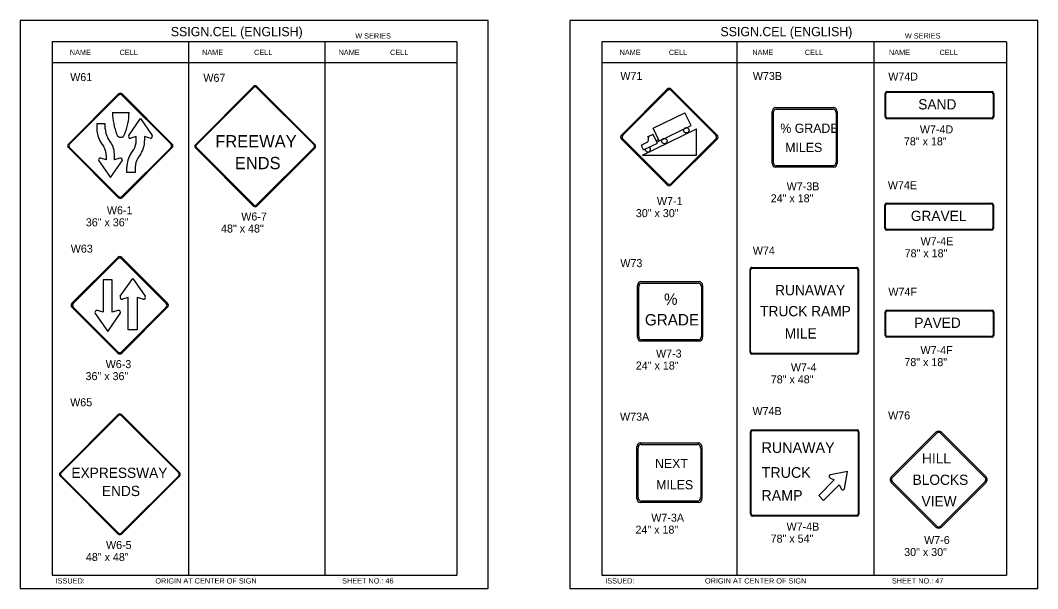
# Model space of a CAD drawing. Extents: x -5299 to 22597, y -19549 to -1808.
# Drawn here: x 2593 to 4118, y -4545 to -3692 of the extents above; entities that cross this region are included whole.
import ezdxf

# ---------------------------------------------------------------- set-up
doc = ezdxf.new("R2010")
doc.units = 0
for name, color, linetype in [('Level 1', 7, 'Continuous'), ('Level 2', 7, 'Continuous'), ('Level 3', 7, 'Continuous'), ('Level 62', 7, 'Continuous')]:
    doc.layers.add(name, color=color, linetype=linetype)

msp = doc.modelspace()

# ---------------------------------------------------------------- linework, layer by layer
at = {"layer": 'Level 1'}
for p, q in [((3247.7, -3724.4), (2640.7, -3724.4)), ((2640.7, -3724.4), (2640.7, -4524.4)), ((2845.3, -3724.4), (2845.3, -4524.4)), ((3049.7, -3725.3), (3049.7, -4525.3)), ((3247.7, -3724.4), (3247.7, -4524.4)), ((4071.6, -3724.4), (3464.6, -3724.4)), ((3464.6, -3724.4), (3464.6, -4524.4)), ((3667, -3724.4), (3667, -4524.4)), ((3872.8, -3723.2), (3872.8, -4523.2)), ((4071.6, -3724.4), (4071.6, -4524.4)), ((3247.7, -3756), (2640.7, -3756)), ((4071.6, -3756), (3464.6, -3756)), ((2855.5, -3878.7), (2942.9, -3791.3)), ((2857.1, -3878.9), (2943.1, -3792.8)), ((2947.3, -3792.8), (3033.4, -3878.9)), ((2947.5, -3791.3), (3034.9, -3878.7)), ((3494.3, -3864.2), (3563, -3795.5)), ((3569, -3795.5), (3637.8, -3864.2)), ((2665.1, -3877.7), (2740.3, -3802.5)), ((2666.9, -3877.9), (2740.5, -3804.3)), ((2745.4, -3804.3), (2819, -3877.9)), ((2745.7, -3802.5), (2820.8, -3877.7)), ((3496.3, -3864.5), (3563.3, -3797.4)), ((3568.8, -3797.4), (3635.8, -3864.5)), ((3889.6, -3837), (3889.6, -3801.7)), ((3890.6, -3836.2), (3890.6, -3802.5)), ((3892.1, -3799), (4049.8, -3799)), ((3892.8, -3800), (4049, -3800)), ((4051.3, -3802.5), (4051.3, -3836.2)), ((4052.3, -3801.7), (4052.3, -3837)), ((3725, -3823.1), (3812.8, -3823.1)), ((3726.4, -3825.4), (3811.4, -3825.4)), ((3971.4, -3819), (3971.4, -3819)), ((2731.2, -3830.2), (2756.1, -3830.2)), ((2755.7, -3864.7), (2773.2, -3839.5)), ((2755.7, -3864.7), (2773.2, -3839.5)), ((2773.2, -3839.5), (2790.6, -3864.7)), ((2773.2, -3839.5), (2790.6, -3864.7)), ((3541.8, -3854), (3589.2, -3830.9)), ((3598.6, -3850.1), (3589.2, -3830.9)), ((3720.1, -3906.6), (3720.1, -3829.1)), ((3722, -3904.9), (3722, -3830.8)), ((3815.9, -3830.8), (3815.9, -3904.9)), ((3817.7, -3829.1), (3817.7, -3906.6)), ((4049.8, -3839.7), (3892.1, -3839.7)), ((4049, -3838.7), (3892.8, -3838.7)), ((2707.9, -3847.2), (2707.9, -3855)), ((2720.4, -3847.2), (2707.9, -3847.2)), ((2720.4, -3855), (2720.4, -3847.2)), ((3525.6, -3894.6), (3606.8, -3855)), ((3551, -3872.8), (3541.8, -3854)), ((3547.5, -3875), (3598.6, -3850.1)), ((3606.8, -3894.6), (3606.8, -3855)), ((2728.5, -3874.9), (2724.3, -3868.5)), ((2767, -3866.2), (2758.8, -3868.8)), ((2767, -3866.2), (2758.8, -3868.8)), ((2767, -3872.4), (2767, -3866.2)), ((2787.5, -3868.8), (2779.4, -3866.2)), ((2779.4, -3866.2), (2779.4, -3872.4)), ((3563, -3939), (3494.3, -3870.2)), ((3563.3, -3937), (3496.3, -3870)), ((3533.5, -3866.8), (3541.7, -3862.8)), ((3534.7, -3866.2), (3533.7, -3874.4)), ((3548.2, -3876.4), (3541.5, -3862.7)), ((3546.9, -3872.3), (3550.2, -3870.7)), ((3565.9, -3866.9), (3565.9, -3866.9)), ((3635.8, -3870), (3568.8, -3937)), ((3637.8, -3870.2), (3569, -3939)), ((3768.6, -3866.8), (3768.6, -3866.8)), ((2740.3, -3958.2), (2665.1, -3883)), ((2740.5, -3956.4), (2666.9, -3882.8)), ((2713.8, -3875.2), (2718.1, -3881.7)), ((2743, -3880.4), (2743, -3880.4)), ((2819, -3882.8), (2745.4, -3956.4)), ((2820.8, -3883), (2745.7, -3958.2)), ((2758.9, -3892.3), (2763.1, -3885.8)), ((2942.9, -3970.7), (2855.5, -3883.3)), ((2943.1, -3969.1), (2857.1, -3883.1)), ((2945.2, -3881), (2945.2, -3881)), ((3033.4, -3883.1), (2947.3, -3969.1)), ((3034.9, -3883.3), (2947.5, -3970.7)), ((3527.4, -3886.6), (3524.4, -3880.4)), ((3525, -3878.7), (3533.7, -3874.4)), ((3527.4, -3886.6), (3548.2, -3876.4)), ((2710.6, -3902.8), (2728.1, -3928)), ((2721.9, -3901.3), (2713.7, -3898.7)), ((2721.9, -3895.1), (2721.9, -3901.3)), ((2728.1, -3928), (2745.6, -3902.8)), ((2734.3, -3901.3), (2734.3, -3895.1)), ((2742.5, -3898.7), (2734.3, -3901.3)), ((2773.6, -3892.6), (2769.4, -3899)), ((3525.6, -3894.6), (3606.8, -3894.6)), ((2753, -3920.3), (2753, -3912.5)), ((2765.4, -3912.5), (2765.4, -3920.3)), ((3812.8, -3912.6), (3725, -3912.6)), ((3811.4, -3910.4), (3726.4, -3910.4)), ((2765.4, -3920.3), (2753, -3920.3)), ((3889.3, -4004.3), (3889.3, -3969)), ((3890.2, -4003.5), (3890.2, -3969.8)), ((3891.8, -3966.3), (4049.4, -3966.3)), ((3892.5, -3967.3), (4048.7, -3967.3)), ((4051, -3969.8), (4051, -4003.5)), ((4051.9, -3969), (4051.9, -4004.3)), ((3971.4, -3985.4), (3971.4, -3985.4)), ((4049.4, -4007), (3891.8, -4007)), ((4048.7, -4006), (3892.5, -4006)), ((2670.4, -4116.6), (2739.2, -4047.8)), ((2672.4, -4116.8), (2739.4, -4049.8)), ((2744.9, -4049.8), (2811.9, -4116.8)), ((2745.1, -4047.8), (2813.9, -4116.6)), ((3687, -4189.6), (3687, -4066)), ((3687, -4189.6), (3687, -4066)), ((3687.9, -4188.7), (3687.9, -4067)), ((3689.5, -4062.8), (3847.1, -4062.8)), ((3689.5, -4062.8), (3847.1, -4062.8)), ((3690.2, -4064), (3846.4, -4064)), ((3848.7, -4067), (3848.7, -4188.7)), ((3849.6, -4066), (3849.6, -4189.6)), ((3849.6, -4066), (3849.6, -4189.6)), ((2730.7, -4081.3), (2717.5, -4081.3)), ((2717.5, -4081.3), (2717.5, -4130.1)), ((2730.7, -4130.1), (2730.7, -4081.3)), ((2743, -4106.1), (2761.8, -4079.2)), ((2761.8, -4079.2), (2780.3, -4106.1)), ((3523.2, -4084), (3611, -4084)), ((3524.6, -4086.2), (3609.6, -4086.2)), ((3518.3, -4167.5), (3518.3, -4089.9)), ((3520.2, -4165.8), (3520.2, -4091.7)), ((3614.1, -4091.7), (3614.1, -4165.8)), ((3615.9, -4089.9), (3615.9, -4167.5)), ((2755, -4107.8), (2746.3, -4110.5)), ((2755, -4156.6), (2755, -4107.8)), ((2777.1, -4110.5), (2768.4, -4107.8)), ((2768.4, -4107.8), (2768.4, -4156.6)), ((2739.2, -4191.3), (2670.4, -4122.6)), ((2739.4, -4189.3), (2672.4, -4122.3)), ((2705.3, -4131.8), (2724.1, -4158.8)), ((2717.5, -4130.1), (2708.7, -4127.5)), ((2724.1, -4158.8), (2742.7, -4131.8)), ((2739.4, -4127.5), (2730.7, -4130.1)), ((2741.7, -4119.5), (2741.7, -4119.5)), ((2811.9, -4122.3), (2744.9, -4189.3)), ((2813.9, -4122.6), (2745.1, -4191.3)), ((3567.2, -4128.7), (3567.2, -4128.7)), ((3768.2, -4128.4), (3768.2, -4128.4)), ((3889.6, -4164.7), (3889.6, -4129.5)), ((3890.6, -4163.9), (3890.6, -4130.3)), ((3892.1, -4126.8), (4049.8, -4126.8)), ((3892.8, -4127.8), (4049, -4127.8)), ((4051.3, -4130.3), (4051.3, -4163.9)), ((4052.3, -4129.5), (4052.3, -4164.7)), ((3970.7, -4145.4), (3970.7, -4145.4)), ((2768.4, -4156.6), (2755, -4156.6)), ((3611, -4173.5), (3523.2, -4173.5)), ((3609.6, -4171.2), (3524.6, -4171.2)), ((4049.8, -4167.4), (3892.1, -4167.4)), ((4049, -4166.4), (3892.8, -4166.4)), ((3847.1, -4192.9), (3689.5, -4192.9)), ((3847.1, -4192.9), (3689.5, -4192.9)), ((3847.1, -4192.9), (3689.5, -4192.9)), ((3846.4, -4191.6), (3690.2, -4191.6)), ((2652.6, -4370.7), (2740, -4283.3)), ((2654.2, -4370.9), (2740.2, -4284.8)), ((2744.4, -4284.8), (2830.5, -4370.9)), ((2744.6, -4283.3), (2832, -4370.7)), ((3687.6, -4432.1), (3687.6, -4309.1)), ((3688.5, -4432.1), (3688.5, -4309.9)), ((3690.1, -4306.1), (3847.7, -4306.1)), ((3690.8, -4307.2), (3847, -4307.2)), ((3849.3, -4309.9), (3849.3, -4432.1)), ((3850.2, -4309.1), (3850.2, -4432.9)), ((3898.6, -4376.8), (3965.5, -4309.9)), ((3900.1, -4378.2), (3966.9, -4311.3)), ((3972.6, -4311.3), (4039.4, -4378.2)), ((3974, -4309.9), (4040.8, -4376.8)), ((3522.1, -4325.9), (3610, -4325.9)), ((3523.6, -4328.1), (3608.5, -4328.1)), ((3517.3, -4409.4), (3517.3, -4331.9)), ((3519.1, -4407.7), (3519.1, -4333.6)), ((3613, -4333.6), (3613, -4407.7)), ((3614.8, -4331.9), (3614.8, -4409.4)), ((2740, -4462.7), (2652.6, -4375.3)), ((2740.2, -4461.1), (2654.2, -4375.1)), ((2742.4, -4373), (2742.4, -4373)), ((2830.5, -4375.1), (2744.4, -4461.1)), ((2832, -4375.3), (2744.6, -4462.7)), ((3566.9, -4370.7), (3566.9, -4370.7)), ((3768.8, -4370.7), (3768.8, -4370.7)), ((3833.1, -4369), (3807.4, -4373.8)), ((3828.5, -4394.8), (3833.1, -4369)), ((3813.2, -4381.5), (3789.9, -4404.8)), ((3797.3, -4412.3), (3820.7, -4388.9)), ((3806.8, -4378.1), (3813.2, -4381.5)), ((3820.7, -4388.9), (3824.1, -4395.4)), ((3965.5, -4452.1), (3898.6, -4385.3)), ((3966.9, -4450.7), (3900.1, -4383.9)), ((3969.6, -4381.3), (3969.6, -4381.3)), ((4039.4, -4383.9), (3972.6, -4450.7)), ((4040.8, -4385.3), (3974, -4452.1)), ((3789.9, -4404.8), (3797.3, -4412.3)), ((3610, -4415.4), (3522.1, -4415.4)), ((3608.5, -4413.2), (3523.6, -4413.2)), ((3847.7, -4435.9), (3690.1, -4435.9)), ((3847, -4434.8), (3690.8, -4434.8)), ((2640.7, -4524.4), (3247.7, -4524.4)), ((3464.6, -4524.4), (4071.6, -4524.4))]:
    msp.add_line(p, q, dxfattribs=at)
for centre in [(3591.5, -3857), (3558.6, -3873.2)]:
    msp.add_circle(centre, 4.03, dxfattribs=at)
for centre, radius, start, end in [((2945.2, -3793.6), 3.25, 45, 135), ((2945.2, -3794.9), 2.98, 45, 135), ((3566, -3798.4), 4.23, 45, 135), ((3566, -3800.2), 3.88, 45, 135), ((2743, -3805.2), 3.8, 45, 135), ((2743, -3806.8), 3.48, 45, 135), ((2825.1, -3828.8), 93.8, 180.8032, 201.7205), ((2662.1, -3828.8), 94, 338.2914, 359.1848), ((2745.5, -3854.9), 37.6, 180.1139, 212.7545), ((2745.3, -3855), 24.9, 180.0457, 212.8226), ((2743.7, -3861.2), 6.24, 202.1766, 337.8234), ((2758, -3866.2), 2.74, 147.86, 286.7479), ((2758, -3866.2), 2.74, 147.86, 286.7479), ((2741.8, -3872.4), 25.2, 327.9451, 359.8882), ((2741.6, -3872.4), 37.8, 327.7467, 359.8501), ((2788.3, -3866.2), 2.74, 253.2521, 32.14), ((3497.3, -3867.2), 4.23, 135, 225), ((3499, -3867.2), 3.88, 135, 225), ((3633.1, -3867.2), 3.88, 315, 45), ((3634.8, -3867.2), 4.23, 315, 45), ((2667.8, -3880.4), 3.8, 135, 225), ((2669.4, -3880.4), 3.48, 135, 225), ((2696.7, -3895.1), 25.2, 0.1119, 32.0549), ((2696.6, -3895.1), 37.8, 0.1499, 32.2533), ((2816.5, -3880.4), 3.48, 315, 45), ((2818.1, -3880.4), 3.8, 315, 45), ((2857.8, -3881), 3.25, 135, 225), ((2859.2, -3881), 2.98, 135, 225), ((3031.3, -3881), 2.98, 315, 45), ((3032.6, -3881), 3.25, 315, 45), ((3525.5, -3879.8), 1.27, 115.9906, 205.9854), ((3533.8, -3885.6), 4.03, 177.4374, 58.7156), ((2712.9, -3901.3), 2.74, 73.2521, 212.14), ((2743.3, -3901.3), 2.74, 327.86, 106.7479), ((2790.5, -3912.6), 37.6, 147.2455, 179.8861), ((2790.4, -3912.5), 24.9, 147.1774, 179.9543), ((3566, -3936), 4.23, 225, 315), ((3566, -3934.2), 3.88, 225, 315), ((2743, -3955.5), 3.8, 225, 315), ((2743, -3953.9), 3.48, 225, 315), ((2945.2, -3968.4), 3.25, 225, 315), ((2945.2, -3967), 2.98, 225, 315), ((2742.2, -4050.8), 4.23, 45, 135), ((2742.2, -4052.5), 3.88, 45, 135), ((2673.4, -4119.6), 4.23, 135, 225), ((2675.1, -4119.6), 3.88, 135, 225), ((2745.5, -4107.7), 2.92, 148.533, 286.6041), ((2777.9, -4107.7), 2.89, 252.0487, 32.8141), ((2809.2, -4119.6), 3.88, 315, 45), ((2810.9, -4119.6), 4.23, 315, 45), ((2707.9, -4130.3), 2.92, 73.3959, 211.467), ((2740.3, -4130.3), 2.89, 327.1859, 107.9513), ((2742.2, -4188.3), 4.23, 225, 315), ((2742.2, -4186.6), 3.88, 225, 315), ((2742.3, -4285.6), 3.25, 45, 135), ((2742.3, -4287), 2.98, 45, 135), ((3969.7, -4314.2), 6, 45.0004, 135.0002), ((3969.7, -4314.2), 4, 45.0004, 135.0002), ((2654.9, -4373), 3.25, 135, 225), ((2656.3, -4373), 2.98, 135, 225), ((2828.3, -4373), 2.98, 315, 45), ((2829.7, -4373), 3.25, 315, 45), ((3807.9, -4376), 2.3, 102.1859, 242.9513), ((3902.9, -4381), 6, 135.0002, 225.0004), ((4036.6, -4381), 6, 314.9998, 45.0004), ((3902.9, -4381), 4, 135.0002, 225.0004), ((4036.6, -4381), 4, 314.9998, 45.0004), ((3826.2, -4394.2), 2.32, 208.3959, 346.467), ((3969.7, -4447.9), 6, 225.0004, 314.9998), ((3969.7, -4447.9), 4, 225.0004, 314.9998), ((2742.3, -4460.4), 3.25, 225, 315), ((2742.3, -4459), 2.98, 225, 315)]:
    msp.add_arc(centre, radius, start, end, dxfattribs=at)
for centre, major_axis, ratio, start_param, end_param in [((3892.1, -3801.7), (0, -2.71), 0.923079, 3.141593, 4.712389), ((3892.8, -3802.5), (0, 2.48), 0.923079, 0, 1.570796), ((4049, -3802.5), (0, 2.48), 0.923079, 4.712389, 6.283185), ((4049.8, -3801.7), (0, 2.71), 0.923079, 4.712389, 6.283185), ((3725, -3829.1), (0, -5.97), 0.817773, 3.141593, 4.712389), ((3726.4, -3830.8), (0, 5.47), 0.817773, 0, 1.570796), ((3811.4, -3830.8), (0, 5.47), 0.817773, 4.712389, 6.283185), ((3812.8, -3829.1), (0, 5.97), 0.817773, 4.712389, 6.283185), ((3892.1, -3837), (0, -2.71), 0.923079, 4.712389, 6.283185), ((3892.8, -3836.2), (0, -2.48), 0.923079, 4.712389, 6.283185), ((4049, -3836.2), (0, -2.48), 0.923079, 0, 1.570796), ((4049.8, -3837), (0, 2.71), 0.923079, 3.141593, 4.712389), ((3725, -3906.6), (0, -5.97), 0.817773, 4.712389, 6.283185), ((3726.4, -3904.9), (0, -5.47), 0.817773, 4.712389, 6.283185), ((3811.4, -3904.9), (0, -5.47), 0.817773, 0, 1.570796), ((3812.8, -3906.6), (0, -5.97), 0.817773, 0, 1.570796), ((3891.8, -3969), (0, -2.71), 0.923079, 3.141593, 4.712389), ((3892.5, -3969.8), (0, 2.48), 0.923079, 0, 1.570796), ((4048.7, -3969.8), (0, 2.48), 0.923079, 4.712389, 6.283185), ((4049.4, -3969), (0, 2.71), 0.923079, 4.712389, 6.283185), ((3891.8, -4004.3), (0, -2.71), 0.923079, 4.712389, 6.283185), ((3892.5, -4003.5), (0, -2.48), 0.923079, 4.712389, 6.283185), ((4048.7, -4003.5), (0, -2.48), 0.923079, 0, 1.570796), ((4049.4, -4004.3), (0, 2.71), 0.923079, 3.141593, 4.712389), ((3689.5, -4066), (0, -3.25), 0.769225, 3.141593, 4.712389), ((3689.5, -4066), (0, -3.25), 0.769225, 3.141593, 4.712389), ((3690.2, -4067), (0, -2.98), 0.769225, 3.141593, 4.712389), ((3846.4, -4067), (0, 2.98), 0.769225, 4.712389, 6.283185), ((3847.1, -4066), (0, 3.25), 0.769225, 4.712389, 6.283185), ((3847.1, -4066), (0, 3.25), 0.769225, 4.712389, 6.283185), ((3523.2, -4089.9), (0, -5.97), 0.817773, 3.141593, 4.712389), ((3524.6, -4091.7), (0, 5.47), 0.817773, 0, 1.570796), ((3609.6, -4091.7), (0, 5.47), 0.817773, 4.712389, 6.283185), ((3611, -4089.9), (0, 5.97), 0.817773, 4.712389, 6.283185), ((3892.1, -4129.5), (0, -2.71), 0.923079, 3.141593, 4.712389), ((3892.8, -4130.3), (0, 2.48), 0.923079, 0, 1.570796), ((4049, -4130.3), (0, 2.48), 0.923079, 4.712389, 6.283185), ((4049.8, -4129.5), (0, 2.71), 0.923079, 4.712389, 6.283185), ((3523.2, -4167.5), (0, -5.97), 0.817773, 4.712389, 6.283185), ((3524.6, -4165.8), (0, -5.47), 0.817773, 4.712389, 6.283185), ((3609.6, -4165.8), (0, -5.47), 0.817773, 0, 1.570796), ((3611, -4167.5), (0, -5.97), 0.817773, 0, 1.570796), ((3892.1, -4164.7), (0, -2.71), 0.923079, 4.712389, 6.283185), ((3892.8, -4163.9), (0, -2.48), 0.923079, 4.712389, 6.283185), ((4049, -4163.9), (0, -2.48), 0.923079, 0, 1.570796), ((4049.8, -4164.7), (0, 2.71), 0.923079, 3.141593, 4.712389), ((3689.5, -4189.6), (0, -3.25), 0.769225, 4.712389, 6.283185), ((3690.2, -4188.7), (0, -2.98), 0.769225, 4.712389, 6.283185), ((3846.4, -4188.7), (0, 2.98), 0.769225, 3.141593, 4.712389), ((3847.1, -4189.6), (0, 3.25), 0.769225, 3.141593, 4.712389), ((3847.1, -4189.6), (0, 3.25), 0.769225, 3.141593, 4.712389), ((3690.1, -4309.1), (0, -2.93), 0.854722, 3.141593, 4.712389), ((3690.8, -4309.9), (0, -2.68), 0.854722, 3.141593, 4.712389), ((3847, -4309.9), (0, 2.68), 0.854722, 4.712389, 6.283185), ((3847.7, -4309.1), (0, 2.93), 0.854722, 4.712389, 6.283185), ((3522.1, -4331.9), (0, -5.97), 0.817773, 3.141593, 4.712389), ((3523.6, -4333.6), (0, 5.47), 0.817773, 0, 1.570796), ((3608.5, -4333.6), (0, 5.47), 0.817773, 4.712389, 6.283185), ((3610, -4331.9), (0, 5.97), 0.817773, 4.712389, 6.283185), ((3522.1, -4409.4), (0, -5.97), 0.817773, 4.712389, 6.283185), ((3523.6, -4407.7), (0, -5.47), 0.817773, 4.712389, 6.283185), ((3608.5, -4407.7), (0, -5.47), 0.817773, 0, 1.570796), ((3610, -4409.4), (0, -5.97), 0.817773, 0, 1.570796), ((3690.1, -4432.9), (0, -2.93), 0.854722, 4.712389, 6.283185), ((3690.8, -4432.1), (0, -2.68), 0.854722, 4.712389, 6.283185), ((3847, -4432.1), (0, -2.68), 0.854722, 0, 1.570796), ((3847.7, -4432.9), (0, -2.93), 0.854722, 0, 1.570796)]:
    msp.add_ellipse(centre, major_axis=major_axis, ratio=ratio, start_param=start_param, end_param=end_param, dxfattribs=at)
at = {"layer": 'Level 62'}
for points in [[(2593.1, -4544.5), (3294.2, -4544.5), (3294.2, -3692.2), (2593.1, -3692.2)], [(3417.1, -4544.5), (4118.2, -4544.5), (4118.2, -3692.2), (3417.1, -3692.2)]]:
    msp.add_lwpolyline(points, close=True, dxfattribs=at)

# ---------------------------------------------------------------- texts
at = {"layer": 'Level 1'}
for s, height, p in [('SAND', 15.37, (3939.2, -3825.8)), (' % GRADE', 13.83, (3727.3, -3860.9)), ('FREEWAY', 18.44, (2885.4, -3882.8)), ('  MILES', 13.83, (3729.5, -3889.7)), ('ENDS', 18.44, (2914.7, -3915.4)), ('GRAVEL', 15.37, (3928, -3993.1)), ('  %', 17.08, (3545.3, -4118.9)), ('RUNAWAY', 15.37, (3724.6, -4104.5)), ('GRADE', 17.08, (3529.4, -4149.8)), ('TRUCK RAMP', 15.37, (3702.2, -4136)), ('PAVED', 15.37, (3933.2, -4153.5)), ('  MILE', 15.37, (3727.6, -4169.5)), ('RUNAWAY', 16, (3704.4, -4341)), ('HILL', 15.37, (3944.8, -4356.8)), ('NEXT', 13.83, (3544.5, -4363.7)), ('EXPRESSWAY', 15.37, (2669.7, -4378.5)), ('TRUCK', 16, (3704.4, -4378.3)), ('BLOCKS', 15.37, (3930.7, -4388.9)), ('ENDS', 15.37, (2715.4, -4405.7)), ('MILES', 13.83, (3546.3, -4395.6)), ('RAMP', 16, (3704, -4412.7)), ('VIEW', 15.37, (3944.1, -4421.1))]:
    msp.add_text(s, height=height, dxfattribs=at).set_placement(p)
at = {"layer": 'Level 2'}
for s, p in [('W61', (2667.9, -3783.3)), ('W67', (2867.5, -3784.4)), ('W71', (3492.6, -3781.5)), ('W73B', (3691.2, -3781.7)), ('W74D', (3894.2, -3782.5)), ('W74E', (3893.6, -3945.4)), ('W63', (2668.7, -4040.6)), ('W74', (3691.2, -4043.5)), ('W73', (3492.6, -4062.3)), ('W74F', (3894.4, -4105.3)), ('W65', (2667.8, -4271)), ('W73A', (3492.1, -4292.6)), ('W74B', (3690.7, -4284.2)), ('W76', (3894, -4290.7))]:
    msp.add_text(s, height=12, dxfattribs=at).set_placement(p)
at = {"layer": 'Level 3'}
for s, height, p in [('SSIGN.CEL (ENGLISH)', 13.857, (2818.7, -3716)), ('SSIGN.CEL (ENGLISH)', 13.857, (3642.7, -3716)), ('W SERIES', 7.92, (3095.2, -3719.4)), ('W SERIES', 7.92, (3919.1, -3719.4)), ('NAME', 7.92, (2667.3, -3744.2)), ('CELL', 7.92, (2741.9, -3744.2)), ('NAME', 7.92, (2865.5, -3744.2)), ('CELL', 7.92, (2943.5, -3744.2)), ('NAME', 7.92, (3070.2, -3744.2)), ('CELL', 7.92, (3147.4, -3744.2)), ('NAME', 7.92, (3491.4, -3744.2)), ('CELL', 7.92, (3565.4, -3744.2)), ('NAME', 7.92, (3690.4, -3744.2)), ('CELL', 7.92, (3769.1, -3744.2)), ('NAME', 7.92, (3895.2, -3744.2)), ('CELL', 7.92, (3971.1, -3744.2)), ('W7-4D', 12, (3941.6, -3861.7)), ('78" x 18"', 12, (3917.7, -3879.7)), ('W7-3B', 12, (3741.9, -3947.1)), ('W7-1', 12, (3547.4, -3969.3)), ('24" x 18"', 12, (3718, -3965.1)), ('W6-1', 12, (2722.9, -3983.1)), ('W6-7', 12, (2924.3, -3992.4)), ('30" x 30"', 12, (3515.8, -3987.3)), ('36" x 36"', 12, (2691.3, -4001.1)), ('48" x 48"', 12, (2894, -4010.4)), ('W7-4E', 12, (3942.7, -4029.5)), ('78" x 18"', 12, (3918.8, -4047.5)), ('W7-3', 12, (3546.1, -4197.9)), ('W7-4F', 12, (3942.6, -4192.8)), ('W6-3', 12, (2721.1, -4213.8)), ('24" x 18"', 12, (3515.8, -4215.9)), ('W7-4', 12, (3748.3, -4218.6)), ('78" x 18"', 12, (3918.4, -4210.8)), ('36" x 36"', 12, (2690.9, -4231.8)), ('78" x 48"', 12, (3718.1, -4236.6)), ('W7-3A', 12, (3539, -4444.1)), ('24" x 18"', 12, (3515.3, -4462.1)), ('W7-4B', 12, (3741.8, -4457.5)), ('78" x 54"', 12, (3717.9, -4475.5)), ('W7-6', 12, (3948, -4477.6)), ('W6-5', 12, (2721.6, -4485.1)), ('30" x 30"', 12, (3918.1, -4495.6)), ('48" x 48"', 12, (2691.4, -4503.1)), ('ISSUED:', 7.92, (2646, -4536.8)), ('ORIGIN AT CENTER OF SIGN', 7.918, (2795.6, -4536.8)), ('SHEET NO.: 46', 7.918, (3075.5, -4536.8)), ('ISSUED:', 7.92, (3470, -4536.8)), ('ORIGIN AT CENTER OF SIGN', 7.918, (3619.5, -4536.8)), ('SHEET NO.: 47', 7.918, (3899.7, -4536.8))]:
    msp.add_text(s, height=height, dxfattribs=at).set_placement(p)

doc.saveas('drawing.dxf')
